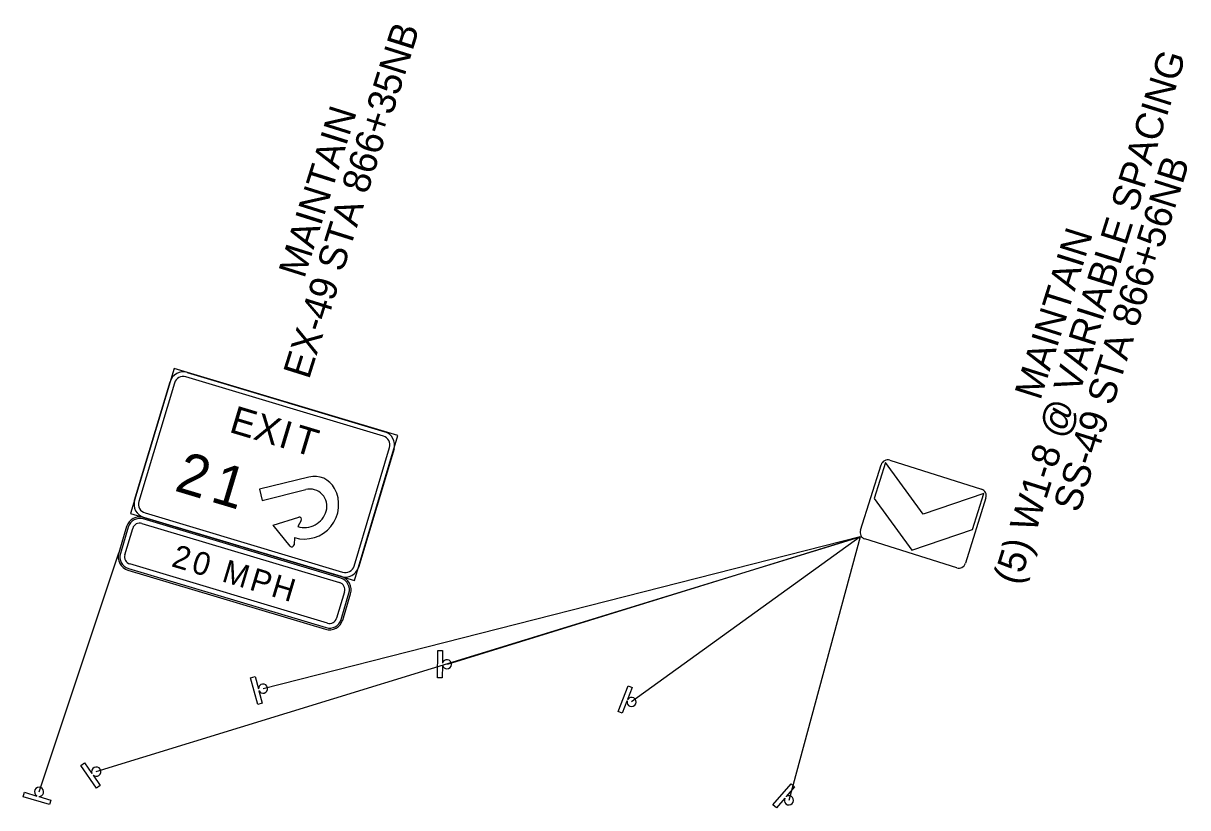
# Model space of a CAD drawing. Extents: x 641128 to 649424, y 422807 to 432853.
# Drawn here: x 644502 to 645010, y 431102 to 431444 of the extents above; entities that cross this region are included whole.
import ezdxf

# ---------------------------------------------------------------- set-up
doc = ezdxf.new("R2010")
doc.units = 0
doc.layers.add('R_Dimension', color=7, linetype='Continuous')
doc.layers.add('S_SIGN', color=7, linetype='Continuous')

msp = doc.modelspace()

# ---------------------------------------------------------------- linework, layer by layer
at = {"layer": 'S_SIGN'}
for p, q in [((644867.55, 431222.6), (644876.56, 431251.22)), ((644894.95, 431229.7), (644878.44, 431252.2)), ((644880.33, 431253.18), (644920.39, 431240.56)), ((644626.92, 431245.86), (644605.34, 431240.52)), ((644626.92, 431245.86), (644605.34, 431240.52)), ((644605.34, 431240.52), (644606.54, 431235.67)), ((644605.34, 431240.52), (644606.54, 431235.67)), ((644605.34, 431240.52), (644606.54, 431235.67)), ((644606.54, 431235.67), (644625.51, 431240.36)), ((644606.54, 431235.67), (644625.51, 431240.36)), ((644921.37, 431238.68), (644894.95, 431229.7)), ((644873.49, 431236.46), (644889.99, 431213.96)), ((644922.35, 431236.8), (644913.34, 431208.19)), ((644641.07, 431202.41), (644554.86, 431228.25)), ((644622.47, 431228.36), (644622.47, 431228.36)), ((644622.47, 431228.36), (644622.47, 431228.36)), ((644547.39, 431224.23), (644543.94, 431212.74)), ((644622.04, 431224.21), (644622.04, 431224.21)), ((644623.6, 431226.89), (644623.6, 431226.89)), ((644534.1, 431117.3), (644867.42, 431219.73)), ((644867.42, 431219.73), (644606.92, 431153.49)), ((644867.42, 431219.73), (644687.21, 431164.03)), ((644867.42, 431219.73), (644767.71, 431147.71)), ((644867.42, 431219.73), (644836.37, 431104.76)), ((644909.57, 431206.23), (644869.51, 431218.84)), ((644889.99, 431213.96), (644916.41, 431222.95)), ((644618.68, 431215.72), (644618.68, 431215.72)), ((644620.43, 431216.33), (644620.43, 431216.33)), ((644620.43, 431216.33), (644620.43, 431216.33)), ((644509.19, 431108.44), (644543.94, 431212.74)), ((644547.97, 431205.26), (644634.18, 431179.42)), ((644641.65, 431183.44), (644645.09, 431194.94)), ((644683.09, 431158.2), (644683.21, 431170.2)), ((644683.21, 431170.2), (644685.21, 431170.18)), ((644685.21, 431170.18), (644685.15, 431164.61)), ((644685.14, 431163.71), (644685.09, 431158.19)), ((644685.2, 431163.71), (644685.14, 431163.71)), ((644685.15, 431164.61), (644685.2, 431164.61)), ((644601.47, 431158.21), (644603.4, 431158.74)), ((644604.66, 431146.64), (644601.47, 431158.21)), ((644603.4, 431158.74), (644604.88, 431153.37)), ((644685.09, 431158.19), (644683.09, 431158.2)), ((644604.88, 431153.37), (644604.92, 431153.38)), ((644605.18, 431152.51), (644605.12, 431152.5)), ((644605.12, 431152.5), (644606.59, 431147.17)), ((644761.8, 431143.57), (644766.16, 431154.75)), ((644768.02, 431154.03), (644766, 431148.83)), ((644766.16, 431154.75), (644768.02, 431154.03)), ((644606.59, 431147.17), (644604.66, 431146.64)), ((644765.67, 431147.99), (644763.67, 431142.84)), ((644765.72, 431147.97), (644765.67, 431147.99)), ((644766, 431148.83), (644766.04, 431148.82)), ((644763.67, 431142.84), (644761.8, 431143.57)), ((644527.41, 431119.95), (644529.06, 431121.09)), ((644534.24, 431110.08), (644527.41, 431119.95)), ((644529.06, 431121.09), (644532.23, 431116.5)), ((644532.23, 431116.5), (644532.27, 431116.53)), ((644532.79, 431115.79), (644532.74, 431115.76)), ((644532.74, 431115.76), (644535.88, 431111.22)), ((644829.41, 431102.85), (644837.28, 431111.91)), ((644837.28, 431111.91), (644838.79, 431110.6)), ((644502.29, 431106.34), (644502.87, 431108.26)), ((644513.78, 431102.88), (644502.29, 431106.34)), ((644502.87, 431108.26), (644508.21, 431106.65)), ((644508.21, 431106.65), (644508.22, 431106.69)), ((644509.09, 431106.44), (644509.07, 431106.39)), ((644509.07, 431106.39), (644514.36, 431104.79)), ((644535.88, 431111.22), (644534.24, 431110.08)), ((644838.79, 431110.6), (644835.14, 431106.39)), ((644835.14, 431106.39), (644835.17, 431106.36)), ((644514.36, 431104.79), (644513.78, 431102.88)), ((644830.92, 431101.54), (644829.41, 431102.85)), ((644834.54, 431105.71), (644830.92, 431101.54)), ((644834.59, 431105.67), (644834.54, 431105.71))]:
    msp.add_line(p, q, dxfattribs=at)
for points in [[(644549.11, 431229.98), (644646.82, 431200.69), (644665.77, 431263.91), (644568.07, 431293.2), (644549.11, 431229.98), (644549.11, 431229.98), (644549.11, 431229.98)], [(644659.45, 431263.71), (644573.24, 431289.56)], [(644573.81, 431291.47), (644660.02, 431265.63)], [(644550.84, 431235.72), (644566.34, 431287.45)], [(644568.26, 431286.88), (644552.75, 431235.15)], [(644568.26, 431286.88), (644568.26, 431286.88), (644568.26, 431286.88)], [(644659.45, 431263.71), (644659.45, 431263.71), (644659.45, 431263.71)], [(644646.62, 431207.01), (644662.13, 431258.73)], [(644664.05, 431258.16), (644648.54, 431206.43)], [(644916.41, 431222.95), (644921.37, 431238.68), (644894.95, 431229.7), (644878.44, 431252.2), (644873.49, 431236.46), (644889.99, 431213.96), (644916.41, 431222.95)], [(644641.07, 431202.41), (644554.86, 431228.25)], [(644555.43, 431230.17), (644641.64, 431204.32)], [(644555.43, 431230.17), (644555.43, 431230.17), (644555.43, 431230.17)], [(644618.68, 431215.72), (644611.39, 431224.79), (644611.39, 431224.79), (644611.39, 431224.79), (644622.47, 431228.36)], [(644548.11, 431224.01), (644544.66, 431212.52)], [(644546.58, 431211.95), (644550.02, 431223.44)], [(644548.11, 431224.01), (644548.11, 431224.01), (644548.11, 431224.01)], [(644554.07, 431225.62), (644640.28, 431199.77)], [(644640.85, 431201.69), (644554.64, 431227.54)], [(644623.6, 431226.89), (644623.6, 431226.89), (644622.04, 431224.21), (644622.04, 431224.21)], [(644620.61, 431219.42), (644620.43, 431216.33)], [(644634.97, 431182.05), (644548.76, 431207.9)], [(644548.18, 431205.98), (644634.39, 431180.14)], [(644548.18, 431205.98), (644548.18, 431205.98), (644548.18, 431205.98)], [(644646.62, 431207.01), (644646.62, 431207.01), (644646.62, 431207.01)], [(644640.85, 431201.69), (644640.85, 431201.69), (644640.85, 431201.69)], [(644642.46, 431195.73), (644639.01, 431184.23)], [(644640.93, 431183.66), (644644.38, 431195.15)], [(644640.93, 431183.66), (644640.93, 431183.66), (644640.93, 431183.66)]]:
    msp.add_lwpolyline(points, dxfattribs=at)
for centre, radius, start, end in [((644572.09, 431285.73), 6, 73.3117, 163.3114), ((644572.09, 431285.73), 4, 73.3117, 163.3114), ((644658.3, 431259.88), 4, 343.3115, 73.3117), ((644658.3, 431259.88), 6, 343.3115, 73.3117), ((644879.43, 431250.32), 3, 72.5211, 162.5213), ((644629.32, 431236.15), 10, 28.2703, 103.9036), ((644629.32, 431236.15), 10, 28.2703, 103.9036), ((644624.91, 431233.79), 15, 253.3115, 28.2703), ((644624.91, 431233.79), 15, 253.3115, 28.2703), ((644627.31, 431233.08), 7.5, 343.6553, 103.9036), ((644627.31, 431233.08), 7.5, 343.6553, 103.9036), ((644919.49, 431237.7), 3, 342.5211, 72.5213), ((644556.58, 431234), 6, 163.3114, 253.3116), ((644556.58, 431234), 4, 163.3114, 253.3116), ((644553.14, 431222.51), 6, 73.3117, 163.3114), ((644624.91, 431233.79), 10, 253.3115, 343.6553), ((644624.91, 431233.79), 10, 253.3115, 343.6553), ((644622.74, 431227.39), 1, 329.8443, 105.5293), ((644553.14, 431222.51), 5.25, 73.3117, 163.3114), ((644553.14, 431222.51), 3.25, 73.3117, 163.3114), ((644870.41, 431221.7), 3, 162.5213, 252.5215), ((644619.43, 431216.38), 1, 221.0967, 356.7799), ((644549.69, 431211.01), 6, 163.3114, 253.3116), ((644549.69, 431211.01), 5.25, 163.3114, 253.3116), ((644549.69, 431211.01), 3.25, 163.3114, 253.3116), ((644910.48, 431209.09), 3, 252.5215, 342.5211), ((644642.79, 431208.16), 6, 253.3116, 343.3118), ((644642.79, 431208.16), 4, 253.3116, 343.3118), ((644639.35, 431196.66), 3.25, 343.3115, 73.3117), ((644639.35, 431196.66), 5.25, 343.3115, 73.3117), ((644639.35, 431196.66), 6, 343.3115, 73.3117), ((644635.9, 431185.17), 6, 253.3116, 343.3118), ((644635.9, 431185.17), 5.25, 253.3116, 343.3118), ((644635.9, 431185.17), 3.25, 253.3116, 343.3118), ((644687.15, 431164.17), 2, 269.4613, 167.1414), ((644687.15, 431164.17), 2, 193.3234, 269.4613), ((644606.92, 431153.49), 2, 285.3967, 183.0768), ((644606.92, 431153.49), 2, 209.2589, 285.3967), ((644767.71, 431147.71), 2, 172.5836, 248.7215), ((644767.71, 431147.71), 2, 248.7215, 146.4016), ((644534.12, 431117.29), 2, 304.6679, 202.348), ((644534.12, 431117.29), 2, 228.53, 304.6679), ((644509.19, 431108.44), 2, 343.208, 240.8881), ((644509.19, 431108.44), 2, 267.0701, 343.208), ((644836.37, 431104.76), 2, 229.0203, 126.7004), ((644836.37, 431104.76), 2, 152.8825, 229.0203)]:
    msp.add_arc(centre, radius, start, end, dxfattribs=at)

# ---------------------------------------------------------------- texts
at = {"layer": 'R_Dimension'}
for s, p in [('EX-49 STA 866+35NB', (644626.93, 431288.1)), ('(5) W1-8 @ VARIABLE SPACING', (644936.78, 431198.22)), ('MAINTAIN', (644624.89, 431332.13)), ('SS-49 STA 866+56NB', (644962.91, 431229.86)), ('MAINTAIN', (644946.05, 431278.96))]:
    msp.add_text(s, height=12, rotation=72.5213, dxfattribs=at).set_placement(p)
at = {"layer": 'S_SIGN'}
for s, height, p in [('E', 12, (644591.67, 431265.63)), ('X', 12, (644602.13, 431262.5)), ('I', 12, (644613.09, 431259.21)), ('T', 12, (644619.37, 431257.33)), ('2', 18, (644567.74, 431240.05)), ('1', 18, (644583.36, 431235.37)), ('2', 10, (644566.52, 431207.01)), ('0', 10, (644575.14, 431204.43)), ('M', 10, (644588.47, 431200.43)), ('P', 10, (644600.47, 431196.83)), ('H', 10, (644609.88, 431194.01))]:
    msp.add_text(s, height=height, rotation=343.3115, dxfattribs=at).set_placement(p)

doc.saveas('drawing.dxf')
